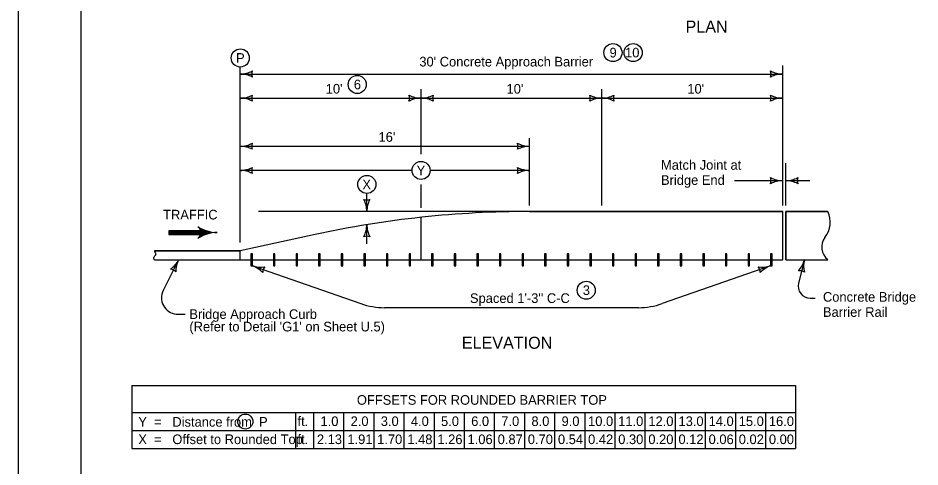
# Model space of a CAD drawing. Extents: x 10028 to 81668, y 6395 to 11634.
# Drawn here: x 10028 to 11525, y 8460 to 9205 of the extents above; entities that cross this region are included whole.
import ezdxf

# ---------------------------------------------------------------- set-up
doc = ezdxf.new("R2010")
doc.units = 0
for name, color, linetype in [('Default', 7, 'Continuous'), ('dsnCellElements', 7, 'Continuous'), ('dsnstdblockInterim', 7, 'Continuous'), ('dsnStdDimension', 7, 'Continuous'), ('ShtPlotIdentification', 7, 'Continuous')]:
    doc.layers.add(name, color=color, linetype=linetype)

msp = doc.modelspace()

# ---------------------------------------------------------------- linework, layer by layer
at = {"layer": 'Default'}
msp.add_lwpolyline([(10132.5, 9944), (13267.5, 9944), (13267.5, 7924), (10132.5, 7924)], close=True, dxfattribs=at)
msp.add_lwpolyline([(10132.5, 9944), (13267.5, 9944), (13267.5, 7924), (10132.5, 7924)], close=True, dxfattribs=at)
at = {"layer": 'dsnCellElements'}
for p, q in [((11296.8, 8884.4), (10876.8, 8884.4)), ((11296.8, 8804.4), (11296.8, 8884.4)), ((11371.8, 8884.4), (11301.8, 8884.4)), ((11301.8, 8884.4), (11301.8, 8804.4)), ((10520.9, 8846.3), (10396.8, 8819.4)), ((10396.8, 8819.4), (10254.5, 8819.4)), ((10254.5, 8804.4), (10396.8, 8804.4)), ((10396.8, 8804.4), (11296.8, 8804.4)), ((11301.8, 8804.4), (11371.8, 8804.4)), ((11010.4, 8491), (11010.4, 8491))]:
    msp.add_line(p, q, dxfattribs=at)
for centre, radius, start, end in [((10876.8, 7203.6), 1680.8, 90, 102.225), ((11335.3, 8866.8), 40.5, 321.0932, 25.7566), ((11388.4, 8825.5), 26.8, 143.687, 231.636)]:
    msp.add_arc(centre, radius, start, end, dxfattribs=at)
msp.add_spline([(10254.5, 8819.4), (10254.4, 8818.3), (10254.9, 8817.4), (10255.6, 8816.2), (10256.1, 8815), (10256.3, 8813.8), (10256.1, 8812.4), (10255.6, 8811.7), (10255.2, 8811), (10254.2, 8810.1), (10253.5, 8808.7), (10253, 8807.5), (10253.3, 8806.1), (10254, 8804.9), (10254.5, 8804.4)], degree=3, dxfattribs=at)
at = {"layer": 'dsnstdblockInterim'}
for points in [[(10132.5, 9944), (13267.5, 9944), (13267.5, 7924), (10132.5, 7924)], [(10132.5, 9939), (13267.5, 9939), (13267.5, 7929), (10132.5, 7929)]]:
    msp.add_lwpolyline(points, close=True, dxfattribs=at)
at = {"layer": 'dsnStdDimension'}
msp.add_lwpolyline([(10028, 7824.5), (13372, 7824.5), (13372, 10408.5), (10028, 10408.5)], close=True, dxfattribs=at)
at = {"layer": 'ShtPlotIdentification'}
for p, q in [((10396.8, 8832.8), (10396.8, 9124.2)), ((11296.8, 8894.4), (11296.8, 9126.7)), ((10396.8, 9112.6), (11296.8, 9112.6)), ((10696.8, 8979.4), (10696.8, 9087.3)), ((10996.8, 8894.4), (10996.8, 9087.3)), ((10396.8, 9072.6), (10696.8, 9072.6)), ((10696.8, 9072.6), (10996.8, 9072.6)), ((10996.8, 9072.6), (11296.8, 9072.6)), ((10876.8, 8894.4), (10876.8, 9006)), ((10396.8, 8992.6), (10876.8, 8992.6)), ((10681.8, 8952.6), (10396.8, 8952.6)), ((10876.8, 8952.6), (10711.8, 8952.6)), ((11301.8, 8894.4), (11301.8, 8964.4)), ((11216.8, 8935.6), (11296.8, 8935.6)), ((11301.8, 8935.6), (11341.8, 8935.6)), ((10696.8, 8890.7), (10696.8, 8929.2)), ((10606.8, 8884.4), (10606.8, 8914.3)), ((10876.8, 8884.4), (10426.8, 8884.4)), ((10696.8, 8804.4), (10696.8, 8874.8)), ((10876.8, 8884.4), (11296.8, 8884.4)), ((11296.8, 8804.4), (11296.8, 8884.4)), ((11301.8, 8884.4), (11371.8, 8884.4)), ((11301.8, 8804.4), (11301.8, 8884.4)), ((10606.8, 8830.7), (10606.8, 8862.6)), ((10331.5, 8849.5), (10278.5, 8849.5)), ((10331.4, 8852.7), (10331.4, 8852.7)), ((10331.4, 8846.5), (10331.4, 8846.5)), ((10520.9, 8846.3), (10396.8, 8819.4)), ((10254.5, 8819.4), (10396.8, 8819.4)), ((10396.8, 8804.4), (10396.8, 8819.4)), ((10254.5, 8804.4), (10396.8, 8804.4)), ((10294.5, 8804.4), (10268.9, 8753.5)), ((10396.8, 8804.4), (11296.8, 8804.4)), ((11301.8, 8804.4), (11371.8, 8804.4)), ((11332.8, 8804.4), (11323.1, 8765.6)), ((10416.8, 8794.4), (10596.7, 8731.5)), ((11276.8, 8794.4), (11096.9, 8731.5)), ((11342.5, 8740.7), (11350.6, 8740.7)), ((10290.2, 8714.1), (10305.6, 8714.1)), ((11057.3, 8724.8), (10636.3, 8724.8)), ((10216.8, 8595.9), (11318.3, 8595.9)), ((10216.8, 8595.9), (10216.8, 8490.9)), ((11318.3, 8595.9), (11318.3, 8490.9)), ((10216.8, 8550.9), (11318.3, 8550.9)), ((10488.3, 8550.9), (10488.3, 8490.9)), ((10518.3, 8550.9), (10518.3, 8490.9)), ((10568.3, 8550.9), (10568.3, 8490.9)), ((10618.3, 8550.9), (10618.3, 8490.9)), ((10668.3, 8550.9), (10668.3, 8490.9)), ((10718.3, 8550.9), (10718.3, 8490.9)), ((10768.3, 8550.9), (10768.3, 8490.9)), ((10818.3, 8550.9), (10818.3, 8490.9)), ((10868.3, 8550.9), (10868.3, 8490.9)), ((10918.3, 8550.9), (10918.3, 8490.9)), ((10968.3, 8550.9), (10968.3, 8490.9)), ((11018.3, 8550.9), (11018.3, 8490.9)), ((11068.3, 8550.9), (11068.3, 8490.9)), ((11118.3, 8550.9), (11118.3, 8490.9)), ((11168.3, 8550.9), (11168.3, 8490.9)), ((11218.3, 8550.9), (11218.3, 8490.9)), ((11268.3, 8550.9), (11268.3, 8490.9)), ((10216.8, 8520.9), (11318.3, 8520.9)), ((10216.8, 8490.9), (11318.3, 8490.9))]:
    msp.add_line(p, q, dxfattribs=at)
for points in [[(10331.4, 8852.5), (10278.5, 8852.5), (10278.5, 8846.5), (10331.4, 8846.5), (10331.2, 8851.6), (10279.1, 8851.8), (10279.3, 8847.1), (10330.2, 8847.3), (10330.4, 8850.9), (10279.9, 8851.1), (10280, 8847.9), (10329.6, 8847.9), (10329.7, 8850.1), (10280.5, 8850.4), (10280.5, 8848.6), (10328.9, 8848.7)], [(10330, 8856.4), (10332.2, 8852.8), (10332.5, 8847.6), (10330.6, 8843), (10338.4, 8846.3), (10347.5, 8848.9), (10350.1, 8849.5), (10343.5, 8850.9), (10333.9, 8854.2), (10331, 8855.7), (10332.1, 8844.6), (10346.2, 8849.3), (10332.4, 8853.5), (10333, 8845.8), (10342.6, 8849.4), (10333.8, 8851.6), (10333.4, 8847.1), (10339.5, 8849.1), (10334.8, 8850.5), (10334.6, 8848.3), (10336.8, 8849)]]:
    msp.add_lwpolyline(points, dxfattribs=at)
for points in [[(10416.8, 8794.4), (10416.8, 8814.4), (10414.3, 8814.4), (10414.3, 8794.4)], [(10454.3, 8794.4), (10454.3, 8814.4), (10451.8, 8814.4), (10451.8, 8794.4)], [(10491.8, 8794.4), (10491.8, 8814.4), (10489.3, 8814.4), (10489.3, 8794.4)], [(10529.3, 8794.4), (10529.3, 8814.4), (10526.8, 8814.4), (10526.8, 8794.4)], [(10566.8, 8794.4), (10566.8, 8814.4), (10564.3, 8814.4), (10564.3, 8794.4)], [(10604.3, 8794.4), (10604.3, 8814.4), (10601.8, 8814.4), (10601.8, 8794.4)], [(10641.8, 8794.4), (10641.8, 8814.4), (10639.3, 8814.4), (10639.3, 8794.4)], [(10679.3, 8794.4), (10679.3, 8814.4), (10676.8, 8814.4), (10676.8, 8794.4)], [(10716.8, 8794.4), (10716.8, 8814.4), (10714.3, 8814.4), (10714.3, 8794.4)], [(10754.3, 8794.4), (10754.3, 8814.4), (10751.8, 8814.4), (10751.8, 8794.4)], [(10791.8, 8794.4), (10791.8, 8814.4), (10789.3, 8814.4), (10789.3, 8794.4)], [(10829.3, 8794.4), (10829.3, 8814.4), (10826.8, 8814.4), (10826.8, 8794.4)], [(10866.8, 8794.4), (10866.8, 8814.4), (10864.3, 8814.4), (10864.3, 8794.4)], [(10904.3, 8794.4), (10904.3, 8814.4), (10901.8, 8814.4), (10901.8, 8794.4)], [(10941.8, 8794.4), (10941.8, 8814.4), (10939.3, 8814.4), (10939.3, 8794.4)], [(10979.3, 8794.4), (10979.3, 8814.4), (10976.8, 8814.4), (10976.8, 8794.4)], [(11016.8, 8794.4), (11016.8, 8814.4), (11014.3, 8814.4), (11014.3, 8794.4)], [(11054.3, 8794.4), (11054.3, 8814.4), (11051.8, 8814.4), (11051.8, 8794.4)], [(11091.8, 8794.4), (11091.8, 8814.4), (11089.3, 8814.4), (11089.3, 8794.4)], [(11129.3, 8794.4), (11129.3, 8814.4), (11126.8, 8814.4), (11126.8, 8794.4)], [(11166.8, 8794.4), (11166.8, 8814.4), (11164.3, 8814.4), (11164.3, 8794.4)], [(11204.3, 8794.4), (11204.3, 8814.4), (11201.8, 8814.4), (11201.8, 8794.4)], [(11241.8, 8794.4), (11241.8, 8814.4), (11239.3, 8814.4), (11239.3, 8794.4)], [(11279.3, 8794.4), (11279.3, 8814.4), (11276.8, 8814.4), (11276.8, 8794.4)]]:
    msp.add_lwpolyline(points, close=True, dxfattribs=at)
for centre, radius in [((11015.2, 9148.1), 15), ((11048.7, 9148.1), 15), ((10396.8, 9139.2), 15), ((10590.9, 9095.2), 15), ((10696.8, 8952.6), 15), ((10606.8, 8929.3), 15), ((10970.8, 8753.8), 15), ((10405.1, 8535.8), 12.5)]:
    msp.add_circle(centre, radius, dxfattribs=at)
for centre, radius, start, end in [((10396.8, 9155.1), 42.5, 270, 298.0725), ((10396.8, 9155.1), 42.5, 270, 298.0725), ((10432.4, 9112.6), 16.4, 162.2666, 197.7334), ((10432.4, 9112.6), 16.4, 162.2666, 197.7334), ((11261.1, 9112.6), 16.4, 342.2666, 17.7333), ((11296.8, 9155.1), 42.5, 241.9275, 270), ((11261.1, 9112.6), 16.4, 342.2666, 17.7333), ((11296.8, 9155.1), 42.5, 241.9275, 270), ((10396.8, 9070.1), 42.5, 61.9275, 90), ((10396.8, 9070.1), 42.5, 61.9275, 90), ((11296.8, 9070.1), 42.5, 90, 118.0725), ((11296.8, 9070.1), 42.5, 90, 118.0725), ((10396.8, 9115.1), 42.5, 270, 298.0725), ((10396.8, 9115.1), 42.5, 270, 298.0725), ((10396.8, 9030.1), 42.5, 61.9275, 90), ((10396.8, 9030.1), 42.5, 61.9275, 90), ((10432.4, 9072.6), 16.4, 162.2666, 197.7334), ((10432.4, 9072.6), 16.4, 162.2666, 197.7334), ((10661.1, 9072.6), 16.4, 342.2666, 17.7333), ((10696.8, 9115.1), 42.5, 241.9275, 270), ((10661.1, 9072.6), 16.4, 342.2666, 17.7333), ((10696.8, 9115.1), 42.5, 241.9275, 270), ((10696.8, 9030.1), 42.5, 90, 118.0725), ((10696.8, 9030.1), 42.5, 90, 118.0725), ((10696.8, 9115.1), 42.5, 270, 298.0725), ((10696.8, 9115.1), 42.5, 270, 298.0725), ((10696.8, 9030.1), 42.5, 61.9275, 90), ((10696.8, 9030.1), 42.5, 61.9275, 90), ((10732.4, 9072.6), 16.4, 162.2666, 197.7334), ((10732.4, 9072.6), 16.4, 162.2666, 197.7334), ((10961.1, 9072.6), 16.4, 342.2666, 17.7333), ((10996.8, 9115.1), 42.5, 241.9275, 270), ((10996.8, 9030.1), 42.5, 90, 118.0725), ((10996.8, 9115.1), 42.5, 270, 298.0725), ((10996.8, 9115.1), 42.5, 270, 298.0725), ((10996.8, 9030.1), 42.5, 61.9275, 90), ((10996.8, 9030.1), 42.5, 61.9275, 90), ((11032.4, 9072.6), 16.4, 162.2666, 197.7334), ((11032.4, 9072.6), 16.4, 162.2666, 197.7334), ((11261.1, 9072.6), 16.4, 342.2666, 17.7333), ((11296.8, 9115.1), 42.5, 241.9275, 270), ((11261.1, 9072.6), 16.4, 342.2666, 17.7333), ((11296.8, 9115.1), 42.5, 241.9275, 270), ((11296.8, 9030.1), 42.5, 90, 118.0725), ((11296.8, 9030.1), 42.5, 90, 118.0725), ((10396.8, 9035.1), 42.5, 270, 298.0725), ((10396.8, 9035.1), 42.5, 270, 298.0725), ((10432.4, 8992.6), 16.4, 162.2666, 197.7334), ((10432.4, 8992.6), 16.4, 162.2666, 197.7334), ((10841.1, 8992.6), 16.4, 342.2666, 17.7333), ((10876.8, 9035.1), 42.5, 241.9275, 270), ((10841.1, 8992.6), 16.4, 342.2666, 17.7333), ((10876.8, 9035.1), 42.5, 241.9275, 270), ((10396.8, 8950.1), 42.5, 61.9275, 90), ((10396.8, 8950.1), 42.5, 61.9275, 90), ((10876.8, 8950.1), 42.5, 90, 118.0725), ((10876.8, 8950.1), 42.5, 90, 118.0725), ((10396.8, 8995.1), 42.5, 270, 298.0725), ((10396.8, 8910.1), 42.5, 61.9275, 90), ((10432.4, 8952.6), 16.4, 162.2666, 197.7334), ((10841.1, 8952.6), 16.4, 342.2666, 17.7333), ((10876.8, 8995.1), 42.5, 241.9275, 270), ((10876.8, 8910.1), 42.5, 90, 118.0725), ((11261.1, 8935.6), 16.4, 342.2666, 17.7333), ((11296.8, 8978.1), 42.5, 241.9275, 270), ((11261.1, 8935.6), 16.4, 342.2666, 17.7333), ((11296.8, 8978.1), 42.5, 241.9275, 270), ((11296.8, 8893.1), 42.5, 90, 118.0725), ((11296.8, 8893.1), 42.5, 90, 118.0725), ((11301.8, 8978.1), 42.5, 270, 298.0725), ((11301.8, 8978.1), 42.5, 270, 298.0725), ((11301.8, 8893.1), 42.5, 61.9275, 90), ((11301.8, 8893.1), 42.5, 61.9275, 90), ((11337.4, 8935.6), 16.4, 162.2666, 197.7334), ((11337.4, 8935.6), 16.4, 162.2666, 197.7334), ((10606.8, 8920.1), 16.4, 252.2666, 287.7333), ((10564.3, 8884.4), 42.5, 360, 28.0725), ((10606.8, 8920.1), 16.4, 252.2666, 287.7333), ((10564.3, 8884.4), 42.5, 360, 28.0725), ((10649.3, 8884.4), 42.5, 151.9275, 180), ((10649.3, 8884.4), 42.5, 151.9275, 180), ((10876.8, 7203.6), 1680.8, 90, 102.225), ((11335.3, 8866.8), 40.5, 321.0932, 25.7566), ((10564.3, 8862.6), 42.5, 331.9275, 360), ((10649.3, 8862.6), 42.5, 180, 208.0725), ((10320.5, 8849.5), 11.3, 301.7147, 58.2853), ((10360.4, 8914), 64.5, 238.2857, 268.3158), ((10360.4, 8785.1), 64.5, 91.6842, 121.7143), ((10606.8, 8827), 16.4, 72.2666, 107.7334), ((11388.4, 8825.5), 26.8, 143.687, 231.636), ((10256.5, 8823.5), 42.5, 305.2525, 333.325), ((10256.5, 8823.5), 42.5, 305.2525, 333.325), ((10332.4, 8785.3), 42.5, 153.325, 181.3975), ((10332.4, 8785.3), 42.5, 153.325, 181.3975), ((11291.6, 8814.7), 42.5, 317.8916, 345.9641), ((11291.6, 8814.7), 42.5, 317.8916, 345.9641), ((11374, 8794.1), 42.5, 165.9641, 194.0366), ((11374, 8794.1), 42.5, 165.9641, 194.0366), ((10278.5, 8772.6), 16.4, 45.5917, 81.0584), ((10278.5, 8772.6), 16.4, 45.5917, 81.0584), ((10430.8, 8834.5), 42.5, 250.7326, 278.8051), ((10402.8, 8754.3), 42.5, 42.6601, 70.7326), ((10450.4, 8782.7), 16.4, 142.9993, 178.466), ((11262.8, 8834.5), 42.5, 261.1949, 289.2674), ((11243.1, 8782.7), 16.4, 1.534, 37.0007), ((11290.8, 8754.3), 42.5, 109.2674, 137.3399), ((11324.2, 8769.8), 16.4, 58.2308, 93.6975), ((11324.2, 8769.8), 16.4, 58.2308, 93.6975), ((11342.5, 8760.7), 20, 165.9638, 270), ((10293.3, 8741.3), 27.3, 153.325, 263.5117), ((10636.3, 8844.8), 120, 250.7327, 270), ((11057.3, 8844.8), 120, 270, 289.2673)]:
    msp.add_arc(centre, radius, start, end, dxfattribs=at)
msp.add_spline([(10254.5, 8819.4), (10254.4, 8818.3), (10254.9, 8817.4), (10255.6, 8816.2), (10256.1, 8815), (10256.3, 8813.8), (10256.1, 8812.4), (10255.6, 8811.7), (10255.2, 8811), (10254.2, 8810.1), (10253.5, 8808.7), (10253, 8807.5), (10253.3, 8806.1), (10254, 8804.9), (10254.5, 8804.4)], degree=3, dxfattribs=at)

# ---------------------------------------------------------------- texts
at = {"layer": 'dsnCellElements'}
for s, height, p in [('PLAN', 20, (11135.6, 9181.3)), ('P', 16, (10389.8, 9131.2)), ("30' Concrete Approach Barrier", 16, (10693.9, 9125.1)), ('6', 16, (10585.2, 9087.2)), ("10'", 16, (10538.6, 9080.1)), ("10'", 16, (10838.6, 9080.1)), ("10'", 16, (11138.6, 9080.1)), ("16'", 16, (10626.2, 9000.1)), ('Match Joint at', 16, (11094.9, 8953.7)), ('Y', 16, (10689.4, 8944.6)), ('X', 16, (10599.4, 8921.3)), ('Bridge End', 16, (11094.9, 8928.6)), ('TRAFFIC', 16, (10268.8, 8871.2)), ('3', 16, (10965.1, 8745.8)), ("Spaced 1'-3'' C-C", 16, (10777.9, 8732.6)), ('Concrete Bridge', 16, (11363.6, 8734.7)), ('Barrier Rail', 16, (11363.6, 8709.6)), ('Bridge Approach Curb', 16, (10312.3, 8706.1)), ("(Refer to Detail 'G1' on Sheet U.5)", 16, (10312.3, 8685.4)), ('ELEVATION', 20, (10764.4, 8656.6)), ('OFFSETS FOR ROUNDED BARRIER TOP', 16, (10590.3, 8563.7)), ('Y  =   Distance from  P', 16, (10227.6, 8527.3)), ('ft.', 16, (10491.7, 8528.4)), ('1.0', 16, (10529.9, 8528.4)), ('2.0', 16, (10579.9, 8528.4)), ('3.0', 16, (10629.9, 8528.4)), ('4.0', 16, (10679.9, 8528.4)), ('5.0', 16, (10729.9, 8528.4)), ('6.0', 16, (10779.9, 8528.4)), ('7.0', 16, (10829.9, 8528.4)), ('8.0', 16, (10879.9, 8528.4)), ('9.0', 16, (10929.9, 8528.4)), ('10.0', 16, (10973.9, 8528.4)), ('11.0', 16, (11023.9, 8528.4)), ('12.0', 16, (11073.9, 8528.4)), ('13.0', 16, (11123.9, 8528.4)), ('14.0', 16, (11173.9, 8528.4)), ('15.0', 16, (11223.9, 8528.4)), ('16.0', 16, (11273.9, 8528.4)), ('X  =   Offset to Rounded Top', 16, (10227.6, 8498.4)), ('ft.', 16, (10491.7, 8498.4)), ('2.13', 16, (10523.9, 8498.4)), ('1.91', 16, (10574.5, 8498.4)), ('1.70', 16, (10623.9, 8498.4)), ('1.48', 16, (10674, 8498.4)), ('1.26', 16, (10723.9, 8498.4)), ('1.06', 16, (10773.9, 8498.4)), ('0.87', 16, (10823.9, 8498.4)), ('0.70', 16, (10873.9, 8498.4)), ('0.54', 16, (10923.9, 8498.4)), ('0.42', 16, (10973.9, 8498.4)), ('0.30', 16, (11023.9, 8498.4)), ('0.20', 16, (11073.9, 8498.4)), ('0.12', 16, (11123.9, 8498.4)), ('0.06', 16, (11173.9, 8498.4)), ('0.02', 16, (11223.9, 8498.4)), ('0.00', 16, (11273.9, 8498.4))]:
    msp.add_text(s, height=height, dxfattribs=at).set_placement(p)
at = {"layer": 'ShtPlotIdentification'}
for s, p in [('9', (11009.5, 9140.1)), ('10', (11035.3, 9140.1))]:
    msp.add_text(s, height=16, dxfattribs=at).set_placement(p)

doc.saveas('drawing.dxf')
